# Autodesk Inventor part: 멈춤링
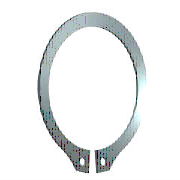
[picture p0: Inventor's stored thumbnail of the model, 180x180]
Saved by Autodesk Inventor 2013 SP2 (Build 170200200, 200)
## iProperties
IsCustomPart: 1
Company: 한국ATC센터
Created: 2014-10
Part Number: 멈춤링
Material: 강, 연강
Description: 리테이닝 링(C형)
Document SubType Name: Modeling
Standard: KS B 1336
Designer: 한국ATC센터
Standards Organization: KS
Language: ko-KR
Size Designation: 25 x 1.2
Categories: <MemberInstance><Categories><Category DisplayName="샤프트 부품" InternalName="7f7aeb1f-a693-4053-b835-cee3144e0d98" Mnemonic="SHFT"><Category DisplayName="써클립" Inter
Density: 7.86 g/cm^3
Mass: 2.3429 g
Surface Area: 7.2498 cm^2
Volume: 0.298079 cm^3
Author: KYOUNG IL JANG
Revision Number: 1
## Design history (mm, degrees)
sketch "스케치1"
  geometry: L1 (-6, 0)-(6, 0) reference; L2 (0, 20.189)-(0, -80.536) reference; L3 (-48.09, 0)-(48.09, 0) reference; L4 (-0.5, -24.44)-(-0.5, -28.74); L5 (-0.5, -6.54)-(-0.5, -13.29); L6 (-2.795, 3.1)-(3.672, 3.1); L7 (0.5, -6.54)-(0.5, -13.29); L8 (0.5, -24.44)-(0.5, -28.74); C1 r 1 at (-2, -26.606); C2 r 1 at (2, -26.606); A1 r 11.95 centre (0, -12.5) between (0.5, -24.44) and (-0.5, -24.44); A2 r 14.825 centre (0, -11.725) between (5.202, -25.608) and (-5.202, -25.608); A3 r 16.247 centre (0, -12.5) between (-2.281, -28.586) and (-0.5, -28.74); A4 r 2 centre (-2, -26.606) between (-3.952, -27.043) and (-2.281, -28.586); A5 r 2 centre (-5.903, -27.48) between (-3.952, -27.043) and (-5.202, -25.608); A6 r 2 centre (5.903, -27.48) between (5.202, -25.608) and (3.952, -27.043); A7 r 2 centre (2, -26.606) between (2.281, -28.586) and (3.952, -27.043); A8 r 16.247 centre (0, -12.5) between (0.5, -28.74) and (2.281, -28.586)
  constraints: 16 point on circle, 12 end point, 10 centre point, 9 symmetric about line, 5 point on line, 4 tangent, 3 coincident, 2 horizontal, 1 perpendicular, 1 vertical, 5 other
  dimensions: "d0" = 23.9 diameter of A1 (= ND); "d1" = 4.3 distance of L4.end L4.start (= SRB2); "d6" = 0.5 distance between parallel lines of L2 L5 (= 0.25 x SD5); "d7" = 3.1 distance between parallel lines of L6 L3 (= SRB1); "d8" = 0.775 distance of A1.centre A2.centre (= 0.25 x SRB1); "d9" = 2 radius of A4 (= SD5); "d10" = 2 radius of A5 (= SD5); "d11" = 1.5 distance from line of L4 A4.centre (= 0.75 x SD5); "d12" = 2 diameter of C1 (= SD5); "d13" = 2 diameter of C2 (= SD5); "d14" = 12.5 distance from line of A1.centre L1 (= 0.5 x WD)
extrude "본체" new body sketch "스케치1" distance "d2" = 1.2 (= SD); taper "d3" = 0 deg
workaxis "Work Axis1"
workplane "Work Plane1"
body "Solid1"
other parameters: "WD" = 25 (= WDMIN) [user parameter; used in 1 equation term], "SD" = 1.2 [user parameter; used in 1 equation term], "SRB1" = 3.1 [user parameter; used in 2 equation terms], "ND" = 23.9 [user parameter; used in 1 equation term], "SRB2" = 4.3 [user parameter; used in 1 equation term], "SD5" = 2 [user parameter; used in 6 equation terms], "d15" = 0, "d16" = 0, "d17" = 0, "d41" = 0, "d42" = 0, "WDMIN" = 25 [user parameter; used in 1 equation term], "SD3" = 23.2 [user parameter], "WDMAX" = 26 [user parameter]
